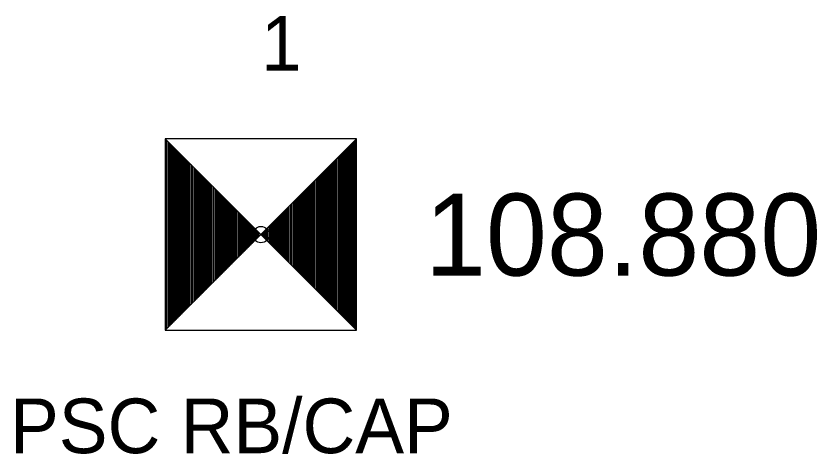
# Model space of a CAD drawing. Extents: x 2529517 to 2532038, y 935000 to 936944.
# Drawn here: x 2529516.67 to 2529531.33, y 935553.36 to 935561.37 of the extents above; entities that cross this region are included whole.
import ezdxf

# ---------------------------------------------------------------- set-up
doc = ezdxf.new("R2010")
doc.units = 0
for name, color, linetype in [('RD_HC_Survey', 7, 'Continuous'), ('RD_HC_Survey_ELEV', 7, 'Continuous'), ('RD_HC_txCode', 7, 'Continuous'), ('RD_SMD_Locator', 7, 'Continuous')]:
    doc.layers.add(name, color=color, linetype=linetype)

msp = doc.modelspace()

# ---------------------------------------------------------------- linework, layer by layer
at = {"layer": 'RD_HC_Survey'}
for p, q in [((2529519.405, 935559.124), (2529522.905, 935555.624)), ((2529522.905, 935559.124), (2529519.405, 935555.624)), ((2529519.43, 935559.099), (2529519.43, 935555.649)), ((2529519.455, 935559.074), (2529519.455, 935555.673)), ((2529519.48, 935559.05), (2529519.48, 935555.698)), ((2529519.504, 935559.025), (2529519.504, 935555.723)), ((2529519.529, 935559), (2529519.529, 935555.748)), ((2529522.782, 935559), (2529522.782, 935555.748)), ((2529522.806, 935559.025), (2529522.806, 935555.723)), ((2529522.831, 935559.05), (2529522.831, 935555.698)), ((2529522.856, 935559.074), (2529522.856, 935555.673)), ((2529522.881, 935559.099), (2529522.881, 935555.649)), ((2529519.554, 935558.975), (2529519.554, 935555.772)), ((2529519.579, 935558.951), (2529519.579, 935555.797)), ((2529519.603, 935558.926), (2529519.603, 935555.822)), ((2529519.628, 935558.901), (2529519.628, 935555.847)), ((2529519.653, 935558.876), (2529519.653, 935555.871)), ((2529519.678, 935558.852), (2529519.678, 935555.896)), ((2529522.633, 935558.852), (2529522.633, 935555.896)), ((2529522.658, 935558.876), (2529522.658, 935555.871)), ((2529522.683, 935558.901), (2529522.683, 935555.847)), ((2529522.707, 935558.926), (2529522.707, 935555.822)), ((2529522.732, 935558.951), (2529522.732, 935555.797)), ((2529522.757, 935558.975), (2529522.757, 935555.772)), ((2529519.702, 935558.827), (2529519.702, 935555.921)), ((2529519.727, 935558.802), (2529519.727, 935555.946)), ((2529519.752, 935558.777), (2529519.752, 935555.97)), ((2529519.777, 935558.753), (2529519.777, 935555.995)), ((2529519.801, 935558.728), (2529519.801, 935556.02)), ((2529519.826, 935558.703), (2529519.826, 935556.045)), ((2529522.485, 935558.703), (2529522.485, 935556.045)), ((2529522.509, 935558.728), (2529522.509, 935556.02)), ((2529522.534, 935558.753), (2529522.534, 935555.995)), ((2529522.559, 935558.777), (2529522.559, 935555.97)), ((2529522.584, 935558.802), (2529522.584, 935555.946)), ((2529522.608, 935558.827), (2529522.608, 935555.921)), ((2529519.851, 935558.678), (2529519.851, 935556.069)), ((2529519.876, 935558.654), (2529519.876, 935556.094)), ((2529519.9, 935558.629), (2529519.9, 935556.119)), ((2529519.925, 935558.604), (2529519.925, 935556.144)), ((2529519.95, 935558.579), (2529519.95, 935556.168)), ((2529519.975, 935558.555), (2529519.975, 935556.193)), ((2529522.336, 935558.555), (2529522.336, 935556.193)), ((2529522.361, 935558.579), (2529522.361, 935556.168)), ((2529522.386, 935558.604), (2529522.386, 935556.144)), ((2529522.41, 935558.629), (2529522.41, 935556.119)), ((2529522.435, 935558.654), (2529522.435, 935556.094)), ((2529522.46, 935558.678), (2529522.46, 935556.069)), ((2529519.999, 935558.53), (2529519.999, 935556.218)), ((2529520.024, 935558.505), (2529520.024, 935556.243)), ((2529520.049, 935558.48), (2529520.049, 935556.267)), ((2529520.074, 935558.456), (2529520.074, 935556.292)), ((2529520.098, 935558.431), (2529520.098, 935556.317)), ((2529520.123, 935558.406), (2529520.123, 935556.342)), ((2529522.188, 935558.406), (2529522.188, 935556.342)), ((2529522.212, 935558.431), (2529522.212, 935556.317)), ((2529522.237, 935558.456), (2529522.237, 935556.292)), ((2529522.262, 935558.48), (2529522.262, 935556.267)), ((2529522.287, 935558.505), (2529522.287, 935556.243)), ((2529522.311, 935558.53), (2529522.311, 935556.218)), ((2529520.148, 935558.381), (2529520.148, 935556.366)), ((2529520.173, 935558.357), (2529520.173, 935556.391)), ((2529520.197, 935558.332), (2529520.197, 935556.416)), ((2529520.222, 935558.307), (2529520.222, 935556.441)), ((2529520.247, 935558.282), (2529520.247, 935556.465)), ((2529520.272, 935558.258), (2529520.272, 935556.49)), ((2529522.039, 935558.258), (2529522.039, 935556.49)), ((2529522.064, 935558.282), (2529522.064, 935556.465)), ((2529522.089, 935558.307), (2529522.089, 935556.441)), ((2529522.113, 935558.332), (2529522.113, 935556.416)), ((2529522.138, 935558.357), (2529522.138, 935556.391)), ((2529522.163, 935558.381), (2529522.163, 935556.366)), ((2529520.296, 935558.233), (2529520.296, 935556.515)), ((2529520.321, 935558.208), (2529520.321, 935556.54)), ((2529520.346, 935558.183), (2529520.346, 935556.564)), ((2529520.371, 935558.159), (2529520.371, 935556.589)), ((2529520.395, 935558.134), (2529520.395, 935556.614)), ((2529520.42, 935558.109), (2529520.42, 935556.639)), ((2529521.891, 935558.109), (2529521.891, 935556.639)), ((2529521.915, 935558.134), (2529521.915, 935556.614)), ((2529521.94, 935558.159), (2529521.94, 935556.589)), ((2529521.965, 935558.183), (2529521.965, 935556.564)), ((2529521.99, 935558.208), (2529521.99, 935556.54)), ((2529522.014, 935558.233), (2529522.014, 935556.515)), ((2529520.445, 935558.084), (2529520.445, 935556.663)), ((2529520.469, 935558.06), (2529520.469, 935556.688)), ((2529520.494, 935558.035), (2529520.494, 935556.713)), ((2529520.519, 935558.01), (2529520.519, 935556.737)), ((2529520.544, 935557.985), (2529520.544, 935556.762)), ((2529520.568, 935557.961), (2529520.568, 935556.787)), ((2529521.742, 935557.961), (2529521.742, 935556.787)), ((2529521.767, 935557.985), (2529521.767, 935556.762)), ((2529521.792, 935558.01), (2529521.792, 935556.737)), ((2529521.816, 935558.035), (2529521.816, 935556.713)), ((2529521.841, 935558.06), (2529521.841, 935556.688)), ((2529521.866, 935558.084), (2529521.866, 935556.663)), ((2529520.593, 935557.936), (2529520.593, 935556.812)), ((2529520.618, 935557.911), (2529520.618, 935556.836)), ((2529520.643, 935557.886), (2529520.643, 935556.861)), ((2529520.667, 935557.862), (2529520.667, 935556.886)), ((2529520.692, 935557.837), (2529520.692, 935556.911)), ((2529520.717, 935557.812), (2529520.717, 935556.935)), ((2529521.594, 935557.812), (2529521.594, 935556.935)), ((2529521.618, 935557.837), (2529521.618, 935556.911)), ((2529521.643, 935557.862), (2529521.643, 935556.886)), ((2529521.668, 935557.886), (2529521.668, 935556.861)), ((2529521.693, 935557.911), (2529521.693, 935556.836)), ((2529521.717, 935557.936), (2529521.717, 935556.812)), ((2529520.742, 935557.787), (2529520.742, 935556.96)), ((2529520.766, 935557.763), (2529520.766, 935556.985)), ((2529520.791, 935557.738), (2529520.791, 935557.01)), ((2529520.816, 935557.713), (2529520.816, 935557.034)), ((2529520.841, 935557.688), (2529520.841, 935557.059)), ((2529520.865, 935557.664), (2529520.865, 935557.084)), ((2529521.445, 935557.664), (2529521.445, 935557.084)), ((2529521.47, 935557.688), (2529521.47, 935557.059)), ((2529521.495, 935557.713), (2529521.495, 935557.034)), ((2529521.519, 935557.738), (2529521.519, 935557.01)), ((2529521.544, 935557.763), (2529521.544, 935556.985)), ((2529521.569, 935557.787), (2529521.569, 935556.96)), ((2529520.89, 935557.639), (2529520.89, 935557.109)), ((2529520.915, 935557.614), (2529520.915, 935557.133)), ((2529520.94, 935557.589), (2529520.94, 935557.158)), ((2529520.964, 935557.565), (2529520.964, 935557.183)), ((2529520.989, 935557.54), (2529520.989, 935557.208)), ((2529521.014, 935557.515), (2529521.014, 935557.232)), ((2529521.297, 935557.515), (2529521.297, 935557.232)), ((2529521.321, 935557.54), (2529521.321, 935557.208)), ((2529521.346, 935557.565), (2529521.346, 935557.183)), ((2529521.371, 935557.589), (2529521.371, 935557.158)), ((2529521.396, 935557.614), (2529521.396, 935557.133)), ((2529521.42, 935557.639), (2529521.42, 935557.109)), ((2529521.039, 935557.49), (2529521.039, 935557.257)), ((2529521.063, 935557.466), (2529521.063, 935557.282)), ((2529521.088, 935557.441), (2529521.088, 935557.307)), ((2529521.113, 935557.416), (2529521.113, 935557.331)), ((2529521.138, 935557.391), (2529521.138, 935557.356)), ((2529521.173, 935557.391), (2529521.173, 935557.356)), ((2529521.198, 935557.416), (2529521.198, 935557.331)), ((2529521.222, 935557.441), (2529521.222, 935557.307)), ((2529521.247, 935557.466), (2529521.247, 935557.282)), ((2529521.272, 935557.49), (2529521.272, 935557.257))]:
    msp.add_line(p, q, dxfattribs=at)
msp.add_lwpolyline([(2529522.905, 935559.124), (2529519.405, 935559.124), (2529519.405, 935555.624), (2529522.905, 935555.624)], close=True, dxfattribs=at)
at = {"layer": 'RD_SMD_Locator'}
msp.add_circle((2529521.155, 935557.374), 0.15, dxfattribs=at)

# ---------------------------------------------------------------- texts
at = {"layer": 'RD_HC_Survey_ELEV'}
msp.add_text('108.880', height=1.5, dxfattribs=at).set_placement((2529524.155, 935556.624))
at = {"layer": 'RD_HC_txCode'}
for s, p in [('1', (2529521.155, 935560.374)), ('PSC RB/CAP', (2529516.565, 935553.374))]:
    msp.add_text(s, height=1, dxfattribs=at).set_placement(p)

doc.saveas('drawing.dxf')
